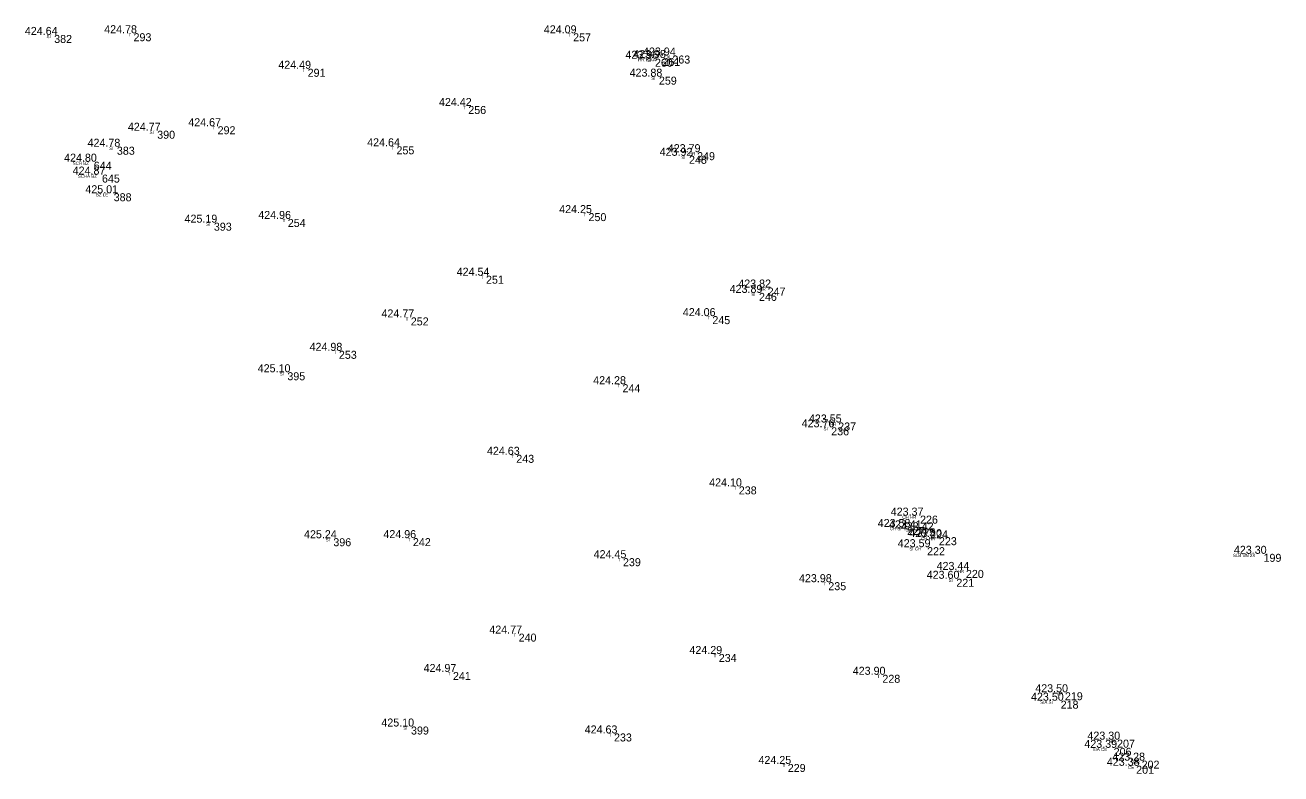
# Model space of a CAD drawing. Extents: x -639373 to -639057, y -1138651 to -1138359.
# Drawn here: x -639312.2 to -639194.5, y -1138500.1 to -1138429.9 of the extents above; entities that cross this region are included whole.
import ezdxf

# ---------------------------------------------------------------- set-up
doc = ezdxf.new("R2010")
doc.units = 0
for name, color, linetype in [('Vrstva 11', 7, 'Continuous'), ('Vrstva 12', 7, 'Continuous'), ('Vrstva 13', 7, 'Continuous'), ('Vrstva 14', 7, 'Continuous'), ('Vrstva 57', 7, 'Continuous')]:
    doc.layers.add(name, color=color, linetype=linetype)

msp = doc.modelspace()

# ---------------------------------------------------------------- linework, layer by layer
at = {"layer": 'Vrstva 11'}
for p, q in [((-639309.8, -1138430.87), (-639309.8, -1138430.87)), ((-639302.36, -1138430.71), (-639302.36, -1138430.71)), ((-639261.15, -1138430.72), (-639261.15, -1138430.72)), ((-639253.48, -1138433.1), (-639253.48, -1138433.1)), ((-639252.78, -1138433.03), (-639252.78, -1138433.03)), ((-639251.85, -1138432.8), (-639251.85, -1138432.8)), ((-639286.04, -1138434.04), (-639286.04, -1138434.04)), ((-639253.11, -1138434.78), (-639253.11, -1138434.78)), ((-639270.98, -1138437.53), (-639270.98, -1138437.53)), ((-639300.14, -1138439.85), (-639300.14, -1138439.85)), ((-639294.48, -1138439.43), (-639294.48, -1138439.43)), ((-639303.92, -1138441.35), (-639303.92, -1138441.35)), ((-639277.71, -1138441.31), (-639277.71, -1138441.31)), ((-639306.09, -1138442.75), (-639306.09, -1138442.75)), ((-639250.29, -1138442.2), (-639250.29, -1138442.2)), ((-639249.53, -1138441.86), (-639249.53, -1138441.86)), ((-639305.32, -1138443.96), (-639305.32, -1138443.96)), ((-639304.22, -1138445.71), (-639304.22, -1138445.71)), ((-639259.71, -1138447.57), (-639259.71, -1138447.57)), ((-639294.83, -1138448.47), (-639294.83, -1138448.47)), ((-639287.9, -1138448.12), (-639287.9, -1138448.12)), ((-639269.32, -1138453.44), (-639269.32, -1138453.44)), ((-639242.92, -1138454.55), (-639242.92, -1138454.55)), ((-639243.73, -1138455.05), (-639243.73, -1138455.05)), ((-639276.37, -1138457.35), (-639276.37, -1138457.35)), ((-639248.1, -1138457.23), (-639248.1, -1138457.23)), ((-639283.11, -1138460.48), (-639283.11, -1138460.48)), ((-639287.94, -1138462.49), (-639287.94, -1138462.49)), ((-639256.52, -1138463.61), (-639256.52, -1138463.61)), ((-639236.3, -1138467.2), (-639236.3, -1138467.2)), ((-639236.96, -1138467.65), (-639236.96, -1138467.65)), ((-639266.48, -1138470.23), (-639266.48, -1138470.23)), ((-639245.62, -1138473.19), (-639245.62, -1138473.19)), ((-639229.85, -1138477), (-639229.85, -1138477)), ((-639228.63, -1138475.93), (-639228.63, -1138475.93)), ((-639283.63, -1138478.05), (-639283.63, -1138478.05)), ((-639276.17, -1138478.04), (-639276.17, -1138478.04)), ((-639228.89, -1138477.13), (-639228.89, -1138477.13)), ((-639227.68, -1138477.31), (-639227.68, -1138477.31)), ((-639226.86, -1138477.95), (-639226.86, -1138477.95)), ((-639227.97, -1138478.89), (-639227.97, -1138478.89)), ((-639256.48, -1138479.92), (-639256.48, -1138479.92)), ((-639196.43, -1138479.51), (-639196.43, -1138479.51)), ((-639224.33, -1138481.02), (-639224.33, -1138481.02)), ((-639237.23, -1138482.17), (-639237.23, -1138482.17)), ((-639225.23, -1138481.85), (-639225.23, -1138481.85)), ((-639266.26, -1138486.99), (-639266.26, -1138486.99)), ((-639247.5, -1138488.9), (-639247.5, -1138488.9)), ((-639272.42, -1138490.59), (-639272.42, -1138490.59)), ((-639232.16, -1138490.85), (-639232.16, -1138490.85)), ((-639215.45, -1138493.28), (-639215.45, -1138493.28)), ((-639215.05, -1138492.49), (-639215.05, -1138492.49)), ((-639276.35, -1138495.7), (-639276.35, -1138495.7)), ((-639257.32, -1138496.35), (-639257.32, -1138496.35)), ((-639210.16, -1138496.93), (-639210.16, -1138496.93)), ((-639210.48, -1138497.7), (-639210.48, -1138497.7)), ((-639241.03, -1138499.21), (-639241.03, -1138499.21)), ((-639208.37, -1138499.38), (-639208.37, -1138499.38)), ((-639207.86, -1138498.9), (-639207.86, -1138498.9))]:
    msp.add_line(p, q, dxfattribs=at)

# ---------------------------------------------------------------- texts
at = {"layer": 'Vrstva 12'}
for s, p in [('424.64 ', (-639312.27, -1138430.87)), ('423.98 ', (-639255.25, -1138433.03)), ('423.94 ', (-639254.32, -1138432.8)), ('424.77 ', (-639302.61, -1138439.85)), ('424.78 ', (-639306.39, -1138441.35)), ('423.79 ', (-639252, -1138441.86)), ('424.80 ', (-639308.59, -1138442.75)), ('424.87 ', (-639307.79, -1138443.96)), ('425.01 ', (-639306.6, -1138445.71)), ('425.19 ', (-639297.3, -1138448.47)), ('423.82 ', (-639245.39, -1138454.55)), ('423.55 ', (-639238.77, -1138467.2)), ('423.37 ', (-639231.1, -1138475.93)), ('423.58 ', (-639232.32, -1138477)), ('423.40 ', (-639229.36, -1138477.95)), ('423.30 ', (-639198.93, -1138479.51)), ('423.44 ', (-639226.8, -1138481.02)), ('423.50 ', (-639217.55, -1138492.49)), ('423.30 ', (-639212.66, -1138496.93))]:
    msp.add_text(s, height=0.75, dxfattribs=at).set_placement(p)
at = {"layer": 'Vrstva 13'}
for s, p in [(' 382', (-639309.8, -1138431.62)), (' 293', (-639302.36, -1138431.46)), (' 257', (-639261.15, -1138431.47)), (' 260', (-639253.48, -1138433.85)), (' 261', (-639252.78, -1138433.78)), (' 263', (-639251.85, -1138433.55)), (' 291', (-639286.04, -1138434.79)), (' 259', (-639253.11, -1138435.53)), (' 256', (-639270.98, -1138438.28)), (' 390', (-639300.14, -1138440.6)), (' 292', (-639294.48, -1138440.18)), (' 383', (-639303.92, -1138442.1)), (' 255', (-639277.71, -1138442.06)), (' 644', (-639306.09, -1138443.5)), (' 248', (-639250.29, -1138442.95)), (' 249', (-639249.53, -1138442.61)), (' 645', (-639305.32, -1138444.71)), (' 388', (-639304.22, -1138446.46)), (' 250', (-639259.71, -1138448.32)), (' 393', (-639294.83, -1138449.22)), (' 254', (-639287.9, -1138448.87)), (' 251', (-639269.32, -1138454.19)), (' 247', (-639242.92, -1138455.3)), (' 246', (-639243.73, -1138455.8)), (' 252', (-639276.37, -1138458.1)), (' 245', (-639248.1, -1138457.98)), (' 253', (-639283.11, -1138461.23)), (' 395', (-639287.94, -1138463.24)), (' 244', (-639256.52, -1138464.36)), (' 237', (-639236.3, -1138467.95)), (' 236', (-639236.96, -1138468.4)), (' 243', (-639266.48, -1138470.98)), (' 238', (-639245.62, -1138473.94)), (' 227', (-639229.85, -1138477.75)), (' 226', (-639228.63, -1138476.68)), (' 396', (-639283.63, -1138478.8)), (' 242', (-639276.17, -1138478.79)), (' 225', (-639228.89, -1138477.88)), (' 224', (-639227.68, -1138478.06)), (' 223', (-639226.86, -1138478.7)), (' 222', (-639227.97, -1138479.64)), (' 239', (-639256.48, -1138480.67)), (' 199', (-639196.43, -1138480.26)), (' 220', (-639224.33, -1138481.77)), (' 235', (-639237.23, -1138482.92)), (' 221', (-639225.23, -1138482.6)), (' 240', (-639266.26, -1138487.74)), (' 234', (-639247.5, -1138489.65)), (' 241', (-639272.42, -1138491.34)), (' 228', (-639232.16, -1138491.6)), (' 218', (-639215.45, -1138494.03)), (' 219', (-639215.05, -1138493.24)), (' 399', (-639276.35, -1138496.45)), (' 233', (-639257.32, -1138497.1)), (' 207', (-639210.16, -1138497.68)), (' 206', (-639210.48, -1138498.45)), (' 229', (-639241.03, -1138499.96)), (' 201', (-639208.37, -1138500.13)), (' 202', (-639207.86, -1138499.65))]:
    msp.add_text(s, height=0.75, dxfattribs=at).set_placement(p)
at = {"layer": 'Vrstva 14'}
for s, p in [('424.78 ', (-639304.83, -1138430.71)), ('424.09 ', (-639263.62, -1138430.72)), ('424.49 ', (-639288.51, -1138434.04)), ('423.96 ', (-639255.97, -1138433.1)), ('423.88 ', (-639255.58, -1138434.78)), ('424.42 ', (-639273.45, -1138437.53)), ('424.67 ', (-639296.95, -1138439.43)), ('424.64 ', (-639280.18, -1138441.31)), ('423.92 ', (-639252.76, -1138442.2)), ('424.96 ', (-639290.39, -1138448.12)), ('424.25 ', (-639262.18, -1138447.57)), ('424.54 ', (-639271.79, -1138453.44)), ('423.89 ', (-639246.2, -1138455.05)), ('424.77 ', (-639278.84, -1138457.35)), ('424.06 ', (-639250.59, -1138457.23)), ('424.98 ', (-639285.58, -1138460.48)), ('425.10 ', (-639290.44, -1138462.49)), ('424.28 ', (-639258.99, -1138463.61)), ('423.76 ', (-639239.45, -1138467.65)), ('424.63 ', (-639268.95, -1138470.23)), ('424.10 ', (-639248.12, -1138473.19)), ('423.41 ', (-639231.27, -1138477.13)), ('423.42 ', (-639230.15, -1138477.31)), ('425.24 ', (-639286.1, -1138478.05)), ('424.96 ', (-639278.66, -1138478.04)), ('423.59 ', (-639230.44, -1138478.89)), ('424.45 ', (-639258.95, -1138479.92)), ('423.98 ', (-639239.7, -1138482.17)), ('423.60 ', (-639227.73, -1138481.85)), ('424.77 ', (-639268.73, -1138486.99)), ('424.29 ', (-639249.97, -1138488.9)), ('424.97 ', (-639274.89, -1138490.59)), ('423.90 ', (-639234.66, -1138490.85)), ('423.50 ', (-639217.95, -1138493.28)), ('425.10 ', (-639278.85, -1138495.7)), ('424.63 ', (-639259.79, -1138496.35)), ('423.39 ', (-639212.95, -1138497.7)), ('423.28 ', (-639210.33, -1138498.9)), ('424.25 ', (-639243.5, -1138499.21)), ('423.38 ', (-639210.84, -1138499.38))]:
    msp.add_text(s, height=0.75, dxfattribs=at).set_placement(p)
at = {"layer": 'Vrstva 57'}
for s, p in [('SI', (-639310.24, -1138431.17)), ('T', (-639302.56, -1138431.01)), ('T', (-639261.35, -1138431.02)), ('HR K KA', (-639254.78, -1138433.33)), ('SI', (-639253.92, -1138433.4)), ('K', (-639252.03, -1138433.1)), ('T', (-639286.24, -1138434.34)), ('SI', (-639253.55, -1138435.08)), ('T', (-639271.18, -1138437.83)), ('SI', (-639300.58, -1138440.15)), ('T', (-639294.68, -1138439.73)), ('SI', (-639304.36, -1138441.65)), ('T', (-639277.91, -1138441.61)), ('SCH BZ', (-639307.78, -1138443.05)), ('SI', (-639250.73, -1138442.5)), ('HR', (-639250.02, -1138442.16)), ('SCHA BZ', (-639307.31, -1138444.26)), ('BZ LE', (-639305.61, -1138446.01)), ('T', (-639259.91, -1138447.87)), ('SI', (-639295.27, -1138448.77)), ('T', (-639288.1, -1138448.42)), ('T', (-639269.52, -1138453.74)), ('HR', (-639243.41, -1138454.85)), ('SI', (-639244.17, -1138455.35)), ('T', (-639276.57, -1138457.65)), ('T', (-639248.3, -1138457.53)), ('T', (-639283.31, -1138460.78)), ('SI', (-639288.38, -1138462.79)), ('T', (-639256.72, -1138463.91)), ('HR', (-639236.79, -1138467.5)), ('SI', (-639237.4, -1138467.95)), ('T', (-639266.68, -1138470.53)), ('T', (-639245.82, -1138473.49)), ('CH SI', (-639231.19, -1138477.3)), ('CH HR', (-639230.02, -1138476.23)), ('SI', (-639284.07, -1138478.35)), ('T', (-639276.37, -1138478.34)), ('SAK', (-639229.67, -1138477.43)), ('SAK', (-639228.46, -1138477.61)), ('CH HR', (-639228.25, -1138478.25)), ('SI CH', (-639229.35, -1138479.19)), ('T', (-639256.68, -1138480.22)), ('SLB VN 2X', (-639199.02, -1138479.81)), ('HR', (-639224.82, -1138481.32)), ('T', (-639237.43, -1138482.47)), ('SI', (-639225.67, -1138482.15)), ('T', (-639266.46, -1138487.29)), ('T', (-639247.7, -1138489.2)), ('T', (-639272.62, -1138490.89)), ('T', (-639232.36, -1138491.15)), ('SIA SI', (-639217.09, -1138493.58)), ('HR', (-639215.54, -1138492.79)), ('SI', (-639276.79, -1138496)), ('T', (-639257.52, -1138496.65)), ('HR', (-639210.65, -1138497.23)), ('SIA CE', (-639212.17, -1138498)), ('T', (-639241.23, -1138499.51)), ('CE', (-639208.86, -1138499.68)), ('HR', (-639208.35, -1138499.2))]:
    msp.add_text(s, height=0.3, dxfattribs=at).set_placement(p)

doc.saveas('drawing.dxf')
